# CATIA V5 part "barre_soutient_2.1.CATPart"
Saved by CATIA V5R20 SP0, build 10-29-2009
Part number: barre_soutient_2.1
Bounding box of the stored display mesh (mm): x 505.778 to 2805.778, y 96.52 to 166.501, z 1069.081 to 1138.848
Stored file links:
  C:\Users\Mike-7\Desktop\MMS_GR3\bfoltzer\CFAO_bfoltzer\barre_soutient_2.1.CATPart
  D:\ecole\thinkmotion\Eolienne.CATProduct
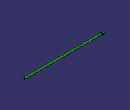
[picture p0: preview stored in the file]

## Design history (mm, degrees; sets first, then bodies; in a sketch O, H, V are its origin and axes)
Set1
  Plane1 "plan dessin": linked copy from another document
  Plane2 "plan début barre": linked copy from another document
  Point1 to Point4: linked copy from another document
  Line1 "axe de rotation": linked copy from another document
Body1 (main body)
  Sketch1 on Plane1, origin (0, 1686.3476, 1266.7707), H (1, 0, 0), V (0, -0.9946, -0.1041)
    line L1 (505.7782, 1583.3373) -> (2805.7782, 1583.3373)
    line L2 (2805.7782, 1583.3373) -> (2805.7782, 1563.3373)
    line L3 (2805.7782, 1563.3373) -> (505.7782, 1563.3373)
    line L4 (505.7782, 1563.3373) -> (505.7782, 1583.3373)
    point P3 (2805.7782, 1563.3373)
    reference projected point E1 (2805.7782, 1563.3373) from Point2
    horizontal: L1 H, L3 H
    vertical: L2 V
    coincidence: P3 E1
  Shaft1: profile Sketch1, axis Line1, angle 360
  Sketch2 on Plane1, origin (0, 1686.3476, 1266.7707), H (1, 0, 0), V (0, -0.9946, -0.1041)
    line L1 (605.7782, 1543.3373) -> (625.7782, 1543.3373)
    line L2 (625.7782, 1543.3373) -> (625.7782, 1528.3373)
    line L3 (625.7782, 1528.3373) -> (605.7782, 1528.3373)
    line L4 (605.7782, 1528.3373) -> (605.7782, 1543.3373)
    point P2 (625.7782, 1543.3373)
    point P4 (605.7782, 1528.3373)
    reference projected point E1 (625.7782, 1543.3373) from Point3
    reference projected point E2 (605.7782, 1528.3373) from Point4
    horizontal: L1 H, L3 H
    vertical: L2 V, L4 V
    coincidence: P2 E1, P4 E2
  Shaft2: profile Sketch2, axis Line1, angle 360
